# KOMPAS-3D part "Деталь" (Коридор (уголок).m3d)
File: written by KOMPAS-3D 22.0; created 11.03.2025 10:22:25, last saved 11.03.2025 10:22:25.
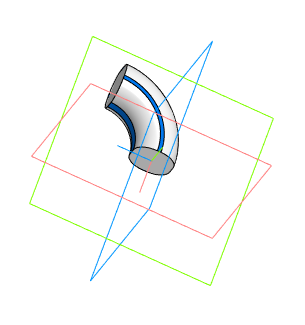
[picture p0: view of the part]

Document properties: Автор: Пользователь Windows; Полное имя файла: C:\Users\Student\Documents\Картошечка\База Сабнатика\Коридор\Коридор (уголок).m3d

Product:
- Part/product: Деталь
    Масса: 0.022497

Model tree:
1. Эскиз:1
2. Элемент вращения:1
     Угол 2 = 90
